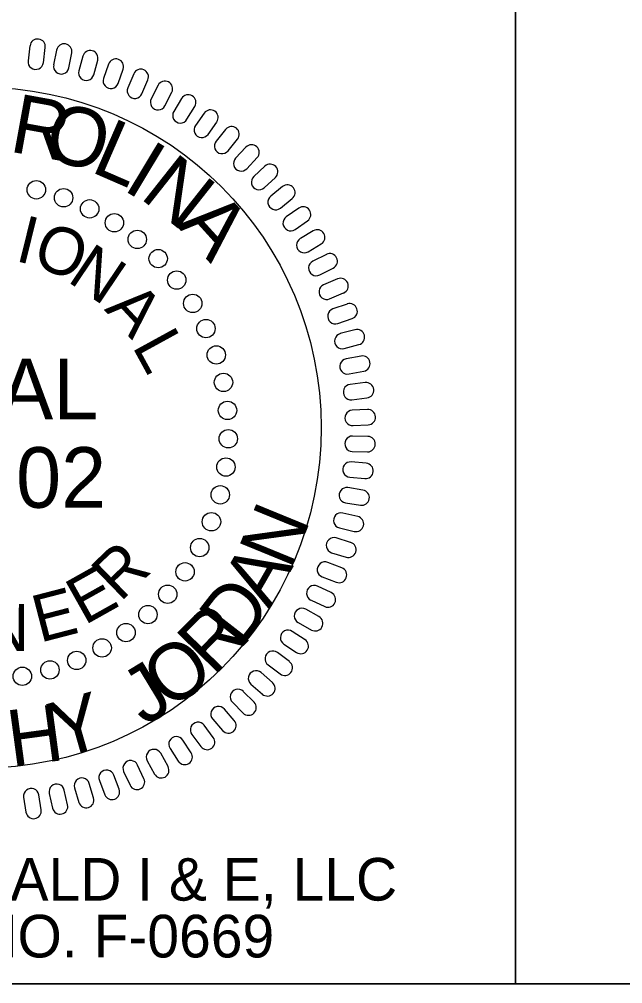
# Model space of a CAD drawing. Extents: x 1901718 to 1902220, y 193828 to 194187.
# Drawn here: x 1902117.63 to 1902123.6, y 193920.51 to 193930.05 of the extents above; entities that cross this region are included whole.
import ezdxf

# ---------------------------------------------------------------- set-up
doc = ezdxf.new("R2010")
doc.units = 0
for name, color, linetype in [('Default', 7, 'Continuous'), ('Old_Level_45', 7, 'Continuous'), ('Scratch_Level_3', 7, 'Continuous'), ('Sheet Border Standard 30in CELL', 7, 'Continuous'), ('Sheet Sticker Exception Certification CELL', 7, 'Continuous')]:
    doc.layers.add(name, color=color, linetype=linetype)

msp = doc.modelspace()

# ---------------------------------------------------------------- linework, layer by layer
at = {"layer": 'Default'}
for p, q in [((1902117.7397, 193929.7919), (1902117.7214, 193929.6432)), ((1902117.8725, 193929.624), (1902117.8909, 193929.7727)), ((1902118.0031, 193929.7493), (1902117.974, 193929.6029)), ((1902118.1237, 193929.5729), (1902118.1529, 193929.7202)), ((1902118.2631, 193929.6884), (1902118.2237, 193929.5441)), ((1902118.3704, 193929.5041), (1902118.4095, 193929.649)), ((1902118.5177, 193929.6101), (1902118.4683, 193929.4681)), ((1902118.6118, 193929.4188), (1902118.6612, 193929.5601)), ((1902118.7663, 193929.5141), (1902118.7076, 193929.3757)), ((1902118.8466, 193929.3164), (1902118.9062, 193929.4539)), ((1902119.0074, 193929.4003), (1902118.9394, 193929.2671)), ((1902119.0739, 193929.1976), (1902119.1428, 193929.3308)), ((1902119.24, 193929.2707), (1902119.1627, 193929.1424)), ((1902119.2929, 193929.0635), (1902119.3702, 193929.1919)), ((1902119.4629, 193929.1249), (1902119.3772, 193929.0017)), ((1902119.501, 193928.9144), (1902119.5877, 193929.0367)), ((1902119.6752, 193928.9635), (1902119.5807, 193928.8473)), ((1902119.6988, 193928.7513), (1902119.7933, 193928.8675)), ((1902119.8762, 193928.7881), (1902119.7739, 193928.6786)), ((1902119.8849, 193928.5747), (1902119.9873, 193928.6842)), ((1902120.0641, 193928.5994), (1902119.9539, 193928.4976)), ((1902120.0574, 193928.3859), (1902120.1675, 193928.4878)), ((1902120.2382, 193928.3974), (1902120.1217, 193928.3038)), ((1902120.2166, 193928.1852), (1902120.3339, 193928.2794)), ((1902120.3985, 193928.1843), (1902120.2749, 193928.0984)), ((1902120.3623, 193927.9735), (1902120.485, 193928.0591)), ((1902120.5425, 193927.9602), (1902120.4145, 193927.8835)), ((1902120.4918, 193927.753), (1902120.6208, 193927.8297)), ((1902120.6716, 193927.7267), (1902120.5378, 193927.6592)), ((1902120.6059, 193927.5233), (1902120.7397, 193927.5914)), ((1902120.7833, 193927.4852), (1902120.6448, 193927.4269)), ((1902120.7037, 193927.2869), (1902120.8422, 193927.3451)), ((1902120.8776, 193927.2357), (1902120.7358, 193927.1877)), ((1902120.7855, 193927.0435), (1902120.9272, 193927.0916)), ((1902120.9549, 193926.9805), (1902120.8099, 193926.9426)), ((1902120.8488, 193926.7952), (1902120.9937, 193926.8341)), ((1902121.0146, 193926.7208), (1902120.8671, 193926.6927)), ((1902120.8961, 193926.5431), (1902121.0427, 193926.5717)), ((1902121.0555, 193926.4574), (1902120.9066, 193926.4396)), ((1902120.9245, 193926.2888), (1902121.0737, 193926.3061)), ((1902121.0781, 193926.1917), (1902120.9282, 193926.1846)), ((1902120.9353, 193926.0322), (1902121.0852, 193926.0402)), ((1902121.082, 193925.9251), (1902120.9319, 193925.9285)), ((1902120.9285, 193925.7763), (1902121.0785, 193925.7735)), ((1902121.0666, 193925.6595), (1902120.9179, 193925.6732)), ((1902120.9037, 193925.5214), (1902121.0529, 193925.5077)), ((1902121.0336, 193925.3946), (1902120.8854, 193925.4185)), ((1902120.8609, 193925.2682), (1902121.0097, 193925.2452)), ((1902120.9816, 193925.1335), (1902120.8359, 193925.1674)), ((1902120.8014, 193925.0191), (1902120.9472, 193924.9853)), ((1902120.912, 193924.876), (1902120.7692, 193924.9206)), ((1902120.7239, 193924.7747), (1902120.8674, 193924.7307)), ((1902120.8247, 193924.6243), (1902120.6849, 193924.6783)), ((1902120.6299, 193924.5369), (1902120.7698, 193924.4829)), ((1902120.72, 193924.3793), (1902120.5841, 193924.4427)), ((1902120.5198, 193924.3058), (1902120.6552, 193924.2418)), ((1902120.5985, 193924.1422), (1902120.4677, 193924.2154)), ((1902120.3935, 193924.0825), (1902120.5243, 193924.0089)), ((1902120.4605, 193923.9138), (1902120.3348, 193923.9958)), ((1902120.3069, 193923.6963), (1902120.1873, 193923.7868)), ((1902120.2513, 193923.8689), (1902120.3769, 193923.7869)), ((1902120.0954, 193923.666), (1902120.2146, 193923.5752)), ((1902120.1383, 193923.4892), (1902120.0258, 193923.5884)), ((1902119.9566, 193923.2952), (1902119.8501, 193923.4016)), ((1902119.926, 193923.4737), (1902120.0385, 193923.3751)), ((1902119.7608, 193923.1144), (1902119.6629, 193923.2277)), ((1902119.7425, 193923.2942), (1902119.848, 193923.1882)), ((1902119.5472, 193923.1279), (1902119.6459, 193923.0147)), ((1902119.5534, 193922.9471), (1902119.4628, 193923.0666)), ((1902119.3417, 193922.9755), (1902119.4313, 193922.8559)), ((1902119.1253, 193922.8383), (1902119.2066, 193922.7125)), ((1902119.3346, 193922.7944), (1902119.2527, 193922.9202)), ((1902119.1058, 193922.658), (1902119.0331, 193922.7892)), ((1902118.8675, 193922.5376), (1902118.8049, 193922.6736)), ((1902118.9003, 193922.7159), (1902118.9721, 193922.5844)), ((1902118.6222, 193922.4342), (1902118.5685, 193922.5742)), ((1902118.6665, 193922.6101), (1902118.73, 193922.4741)), ((1902118.1803, 193922.4474), (1902118.2238, 193922.3041)), ((1902118.3696, 193922.3482), (1902118.3261, 193922.4916)), ((1902118.4269, 193922.5206), (1902118.4796, 193922.3799)), ((1902117.6772, 193922.3548), (1902117.7, 193922.2066)), ((1902117.8504, 193922.23), (1902117.8279, 193922.3782)), ((1902117.9304, 193922.3925), (1902117.964, 193922.2459)), ((1902118.1121, 193922.2802), (1902118.0785, 193922.4261))]:
    msp.add_line(p, q, dxfattribs=at)
for centre in [(1902117.8026, 193928.3659), (1902118.0718, 193928.2868), (1902118.3302, 193928.1775), (1902118.5745, 193928.0395), (1902118.8014, 193927.8746), (1902119.0081, 193927.6848), (1902119.1918, 193927.4728), (1902119.3501, 193927.2411), (1902119.4809, 193926.993), (1902119.5827, 193926.7315), (1902119.654, 193926.4602), (1902119.6938, 193926.1825), (1902119.7018, 193925.902), (1902119.6777, 193925.6225), (1902119.622, 193925.3475), (1902119.5352, 193925.0807), (1902119.4186, 193924.8255), (1902119.2737, 193924.5853), (1902119.1024, 193924.3632), (1902118.9068, 193924.162), (1902118.6896, 193923.9844), (1902118.4536, 193923.8328), (1902118.2018, 193923.709), (1902117.9375, 193923.6148), (1902117.6642, 193923.5513)]:
    msp.add_circle(centre, 0.091, dxfattribs=at)
for centre, start, end in [((1902117.8156, 193929.7823), 352.83494, 172.83432), ((1902118.0779, 193929.7346), 348.83494, 168.83432), ((1902118.3362, 193929.6687), 344.83494, 164.83432), ((1902117.7969, 193929.6336), 172.83432, 352.83494), ((1902118.0488, 193929.5875), 168.83432, 348.83494), ((1902118.5893, 193929.585), 340.83494, 160.83432), ((1902118.297, 193929.5241), 164.83432, 344.83494), ((1902118.8359, 193929.4838), 336.83494, 156.83432), ((1902118.5401, 193929.4434), 160.83432, 340.83494), ((1902119.0749, 193929.3657), 332.83494, 152.83432), ((1902118.777, 193929.346), 156.83432, 336.83494), ((1902119.0065, 193929.2323), 152.83432, 332.83494), ((1902119.305, 193929.2311), 328.83494, 148.83432), ((1902119.2275, 193929.1029), 148.83432, 328.83494), ((1902119.5253, 193929.0809), 324.83494, 144.83432), ((1902119.4389, 193928.9584), 144.83432, 324.83494), ((1902119.7344, 193928.9156), 320.83494, 140.83432), ((1902119.6398, 193928.7994), 140.83432, 320.83494), ((1902119.9316, 193928.7362), 316.83494, 136.83432), ((1902119.8291, 193928.6269), 136.83432, 316.83494), ((1902120.1158, 193928.5435), 312.83494, 132.83432), ((1902120.0058, 193928.4415), 132.83432, 312.83494), ((1902120.286, 193928.3383), 308.83494, 128.83432), ((1902120.1693, 193928.2443), 128.83432, 308.83494), ((1902120.4416, 193928.1218), 304.83494, 124.83432), ((1902120.3185, 193928.0362), 124.83432, 304.83494), ((1902120.4529, 193927.8182), 120.83432, 300.83494), ((1902120.5816, 193927.895), 300.83494, 120.83432), ((1902120.7055, 193927.6589), 296.83494, 116.83432), ((1902120.5718, 193927.5913), 116.83432, 296.83494), ((1902120.6745, 193927.3567), 112.83432, 292.83494), ((1902120.8126, 193927.4148), 292.83494, 112.83432), ((1902120.9025, 193927.1638), 288.83494, 108.83432), ((1902120.7606, 193927.1154), 108.83432, 288.83494), ((1902120.8297, 193926.8688), 104.83432, 284.83494), ((1902120.9746, 193926.9072), 284.83494, 104.83432), ((1902120.8814, 193926.618), 100.83432, 280.83494), ((1902121.0286, 193926.6461), 280.83494, 100.83432), ((1902121.0643, 193926.382), 276.83494, 96.83432), ((1902120.9155, 193926.3641), 96.83432, 276.83494), ((1902120.9318, 193926.1085), 92.83432, 272.83494), ((1902121.0815, 193926.1159), 272.83494, 92.83432), ((1902120.9302, 193925.8524), 88.83432, 268.83494), ((1902121.08, 193925.8493), 268.83494, 88.83432), ((1902120.9107, 193925.597), 84.83432, 264.83494), ((1902121.06, 193925.5835), 264.83494, 84.83432), ((1902120.8735, 193925.3436), 80.83432, 260.83494), ((1902121.0215, 193925.3197), 260.83494, 80.83432), ((1902120.8187, 193925.0934), 76.83432, 256.83494), ((1902120.9647, 193925.0593), 256.83494, 76.83432), ((1902120.7466, 193924.8476), 72.83432, 252.83494), ((1902120.8898, 193924.8034), 252.83494, 72.83432), ((1902120.6576, 193924.6075), 68.83432, 248.83494), ((1902120.7973, 193924.5534), 248.83494, 68.83432), ((1902120.5519, 193924.3742), 64.83432, 244.83494), ((1902120.6876, 193924.3104), 244.83494, 64.83432), ((1902120.4303, 193924.1488), 60.83432, 240.83494), ((1902120.5612, 193924.0757), 240.83494, 60.83432), ((1902120.2932, 193923.9324), 56.83432, 236.83494), ((1902120.4187, 193923.8504), 236.83494, 56.83432), ((1902120.1414, 193923.7261), 52.83432, 232.83494), ((1902120.2609, 193923.6356), 232.83494, 52.83432), ((1902119.9756, 193923.5309), 48.83432, 228.83494), ((1902119.7965, 193923.3478), 44.83432, 224.83494), ((1902120.0884, 193923.4323), 228.83494, 48.83432), ((1902119.6051, 193923.1776), 40.83432, 220.83494), ((1902119.9022, 193923.2415), 224.83494, 44.83432), ((1902119.7032, 193923.0642), 220.83494, 40.83432), ((1902119.4023, 193923.0212), 36.83432, 216.83494), ((1902119.1891, 193922.8792), 32.83432, 212.83494), ((1902119.4922, 193922.9012), 216.83494, 36.83432), ((1902118.9665, 193922.7526), 28.83432, 208.83494), ((1902119.2704, 193922.7533), 212.83494, 32.83432), ((1902118.7356, 193922.6417), 24.83432, 204.83494), ((1902119.0388, 193922.6212), 208.83494, 28.83432), ((1902118.2535, 193922.4696), 16.83432, 196.83494), ((1902118.4976, 193922.5472), 20.83432, 200.83494), ((1902118.0046, 193922.4091), 12.83432, 192.83494), ((1902118.7986, 193922.5057), 204.83494, 24.83432), ((1902117.7521, 193922.3662), 8.83432, 188.83494), ((1902118.2969, 193922.3261), 196.83494, 16.83432), ((1902118.5509, 193922.4071), 200.83494, 20.83432), ((1902118.0379, 193922.263), 192.83494, 12.83432), ((1902117.7751, 193922.2181), 188.83494, 8.83432)]:
    msp.add_arc(centre, 0.0761, start, end, dxfattribs=at)
at = {"layer": 'Scratch_Level_3'}
msp.add_circle((1902117.2512, 193926.0122), 3.37, dxfattribs=at)
at = {"layer": 'Sheet Border Standard 30in CELL'}
msp.add_line((1902122.5436, 193931.7593), (1902122.5436, 193920.5143), dxfattribs=at)
for points in [[(1902112.5386, 193931.7593), (1902122.5436, 193931.7593), (1902122.5436, 193920.5093), (1902112.5386, 193920.5093)], [(1902122.5436, 193931.7593), (1902132.5436, 193931.7593), (1902132.5436, 193920.5093), (1902122.5436, 193920.5093)]]:
    msp.add_lwpolyline(points, close=True, dxfattribs=at)
at = {"layer": 'Sheet Sticker Exception Certification CELL'}
msp.add_line((1902112.5386, 193920.5093), (1902132.5423, 193920.5093), dxfattribs=at)

# ---------------------------------------------------------------- texts
at = {"layer": 'Default'}
for s, height, rotation, p in [('R', 0.5824, 349.6661, (1902117.5231, 193928.7472)), ('O', 0.5824, 345.72703, (1902117.8535, 193928.683)), ('L', 0.5824, 336.51573, (1902118.3267, 193928.5503)), ('I', 0.5824, 328.95921, (1902118.6452, 193928.3728)), ('N', 0.5825, 321.66236, (1902118.8138, 193928.2921)), ('A', 0.5824, 312.13266, (1902119.1826, 193928.0142)), ('I', 0.4672, 346.13834, (1902117.5822, 193927.6649)), ('O', 0.4672, 340.15078, (1902117.7454, 193927.6226)), ('N', 0.4672, 326.04252, (1902118.0974, 193927.4656)), ('A', 0.4672, 312.74665, (1902118.4689, 193927.1799)), ('L', 0.4672, 298.71599, (1902118.7458, 193926.8196)), ('SEAL', 0.59922, 360, (1902116.3662, 193926.0946)), ('N', 0.56, 67.72178, (1902120.3137, 193924.598)), ('R', 0.4672, 44.02408, (1902118.6325, 193924.2787)), ('A', 0.56, 60.25231, (1902120.1038, 193924.2119)), ('E', 0.4672, 29.27885, (1902118.2785, 193924.0523)), ('D', 0.56, 52.07521, (1902119.8188, 193923.8244)), ('E', 0.4672, 14.53374, (1902117.837, 193923.8824)), ('N', 0.4672, 359.78871, (1902117.2802, 193923.8026)), ('R', 0.56, 45.53518, (1902119.5529, 193923.5462)), ('O', 0.56, 36.20685, (1902119.1227, 193923.2058)), ('J', 0.56, 31.1856, (1902118.8699, 193923.0527)), ('Y', 0.56, 15.95094, (1902118.0353, 193922.7314)), ('H', 0.56, 7.69991, (1902117.5564, 193922.6528))]:
    msp.add_text(s, height=height, rotation=rotation, dxfattribs=at).set_placement(p)
msp.add_text('21102', height=0.5994, dxfattribs=at).set_placement((1902116.2647, 193925.2196))
at = {"layer": 'Old_Level_45'}
for s, p in [('MOTT MACDONALD I & E, LLC', (1902113.2847, 193921.3317)), (' LICENSE NO. F-0669', (1902114.4812, 193920.7692))]:
    msp.add_text(s, height=0.421875, rotation=360, dxfattribs=at).set_placement(p)

doc.saveas('drawing.dxf')
